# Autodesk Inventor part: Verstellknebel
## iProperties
Created: 2008-02
Part Number: Verstellknebel
Document SubType Name: Modeling
Designer: Benno
Manufacturer: Standard
Standards Organization: Custom
Author: Benno
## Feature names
1. Drehung1 [Revolution]
2. Bohrung1 [Hole]
3. Fase1 [Chamfer]
4. Fase2 [Chamfer]
